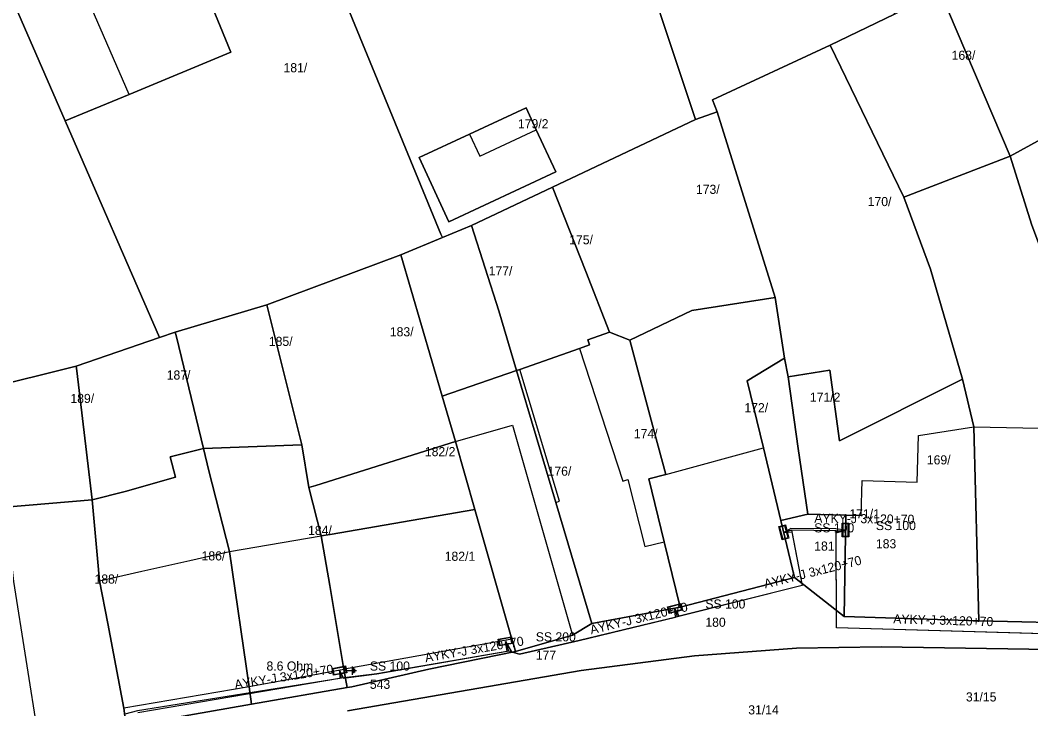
# Model space of a CAD drawing. Extents: x -793400 to -756198, y -1074141 to -1042963.
# Drawn here: x -783672.6 to -783589.5, y -1065252.1 to -1065195.5 of the extents above; entities that cross this region are included whole.
import ezdxf

# ---------------------------------------------------------------- set-up
doc = ezdxf.new("R2010")
doc.units = 0
for name, color, linetype in [('Parcela', 7, 'Continuous'), ('Popiskový text - Parcela', 7, 'Continuous'), ('Popiskový text - Přípojková skříň nn - SJZ', 7, 'Continuous'), ('Popiskový text - Přípojková skříň nn - Typ', 7, 'Continuous'), ('Popiskový text - Uzemnění - Odpor', 7, 'Continuous'), ('Popiskový text - Vedení nn kabelové', 7, 'Continuous'), ('Skříň', 7, 'Continuous'), ('Spojnice nn', 7, 'Continuous'), ('Stavební objekt', 7, 'Continuous'), ('Uzemnění', 7, 'Continuous'), ('Vedení nn kabelové', 7, 'Continuous')]:
    doc.layers.add(name, color=color, linetype=linetype)

msp = doc.modelspace()

# ---------------------------------------------------------------- linework, layer by layer
at = {"layer": 'Parcela'}
for points in [[(-783615.3, -1065203.05), (-783617.06, -1065203.69), (-783628.64, -1065168.91), (-783610.22, -1065163.36), (-783600.72, -1065195.04), (-783605.99, -1065197.59), (-783615.68, -1065202.06)], [(-783635.48, -1065212.41), (-783637.88, -1065213.4), (-783638.01, -1065213.11), (-783652.59, -1065177.6), (-783628.64, -1065168.91), (-783617.06, -1065203.69), (-783628.83, -1065209.24)], [(-783659.84, -1065221.18), (-783661.13, -1065221.62), (-783668.9, -1065203.8), (-783663.64, -1065201.62), (-783655.26, -1065198.14), (-783659.15, -1065188.65), (-783662.03, -1065181.56), (-783658.02, -1065179.74), (-783652.59, -1065177.6), (-783638.01, -1065213.11), (-783637.88, -1065213.4), (-783641.3, -1065214.82), (-783652.31, -1065218.91)], [(-783663.64, -1065201.62), (-783668.9, -1065203.8), (-783675.89, -1065187.8), (-783662.03, -1065181.56), (-783659.15, -1065188.65), (-783655.26, -1065198.14)], [(-783582.95, -1065202.17), (-783591.21, -1065206.69), (-783596.99, -1065193.1), (-783583.72, -1065188.34), (-783565.46, -1065184.47), (-783562.84, -1065196.01)], [(-783683.5, -1065227.58), (-783687.75, -1065229.06), (-783699.64, -1065200.28), (-783675.89, -1065187.8), (-783668.9, -1065203.8), (-783661.13, -1065221.62), (-783667.99, -1065223.97), (-783675.61, -1065225.85)], [(-783591.21, -1065206.69), (-783599.94, -1065210.07), (-783605.99, -1065197.59), (-783600.72, -1065195.04), (-783596.99, -1065193.1)], [(-783557.3, -1065234.49), (-783556.38, -1065246.22), (-783584.39, -1065245.11), (-783584.35, -1065230.9), (-783584.56, -1065230.03), (-783584.78, -1065229.15), (-783586.43, -1065222.48), (-783588, -1065216.15), (-783589.42, -1065212.38), (-783591.21, -1065206.69), (-783582.95, -1065202.17), (-783562.84, -1065196.01), (-783557.84, -1065229.35), (-783557.51, -1065231.83)], [(-783597.74, -1065215.99), (-783595.12, -1065225.03), (-783605.23, -1065230.1), (-783606.04, -1065224.28), (-783609.46, -1065224.84), (-783609.76, -1065223.3), (-783610.52, -1065218.33), (-783615.3, -1065203.05), (-783615.68, -1065202.06), (-783605.99, -1065197.59), (-783599.94, -1065210.07)], [(-783628.54, -1065208), (-783630.16, -1065204.53), (-783631, -1065202.72), (-783635.65, -1065204.89), (-783639.8, -1065206.82), (-783637.34, -1065212.1)], [(-783628.54, -1065208), (-783637.34, -1065212.1), (-783639.8, -1065206.82), (-783635.65, -1065204.89), (-783631, -1065202.72), (-783630.16, -1065204.53)], [(-783617.38, -1065219.39), (-783622.48, -1065221.84), (-783624.13, -1065221.18), (-783626.08, -1065216.18), (-783628.83, -1065209.24), (-783617.06, -1065203.69), (-783615.3, -1065203.05), (-783610.52, -1065218.33)], [(-783584.35, -1065230.9), (-783584.39, -1065245.11), (-783593.79, -1065244.89), (-783594.19, -1065228.95), (-783595.12, -1065225.03), (-783597.74, -1065215.99), (-783599.94, -1065210.07), (-783591.21, -1065206.69), (-783589.42, -1065212.38), (-783588, -1065216.15), (-783586.43, -1065222.48), (-783584.78, -1065229.15), (-783584.56, -1065230.03)], [(-783631.51, -1065224.23), (-783631.79, -1065224.31), (-783633.23, -1065219.42), (-783635.48, -1065212.41), (-783628.83, -1065209.24), (-783626.08, -1065216.18), (-783624.13, -1065221.18), (-783625.93, -1065221.8), (-783625.79, -1065222.22), (-783626.6, -1065222.5)], [(-783631.79, -1065224.31), (-783637.89, -1065226.43), (-783641.3, -1065214.82), (-783637.88, -1065213.4), (-783635.48, -1065212.41), (-783633.23, -1065219.42)], [(-783648.29, -1065233.77), (-783648.87, -1065233.95), (-783649.42, -1065230.44), (-783652.31, -1065218.91), (-783641.3, -1065214.82), (-783637.89, -1065226.43), (-783636.8, -1065230.16)], [(-783608.92, -1065241.34), (-783618.33, -1065243.78), (-783619.65, -1065238.4), (-783620.92, -1065233.24), (-783619.52, -1065232.86), (-783620.49, -1065229.23), (-783622.48, -1065221.84), (-783617.38, -1065219.39), (-783610.52, -1065218.33), (-783609.76, -1065223.3), (-783612.82, -1065225.16), (-783611.49, -1065230.69), (-783610.05, -1065236.65)], [(-783649.42, -1065230.44), (-783657.52, -1065230.72), (-783659.74, -1065221.56), (-783659.84, -1065221.18), (-783652.31, -1065218.91)], [(-783663.95, -1065234.27), (-783666.67, -1065234.95), (-783667.94, -1065224.36), (-783667.99, -1065223.97), (-783661.13, -1065221.62), (-783659.84, -1065221.18), (-783659.74, -1065221.56), (-783657.52, -1065230.72), (-783660.27, -1065231.42), (-783659.82, -1065233.08)], [(-783618.33, -1065243.78), (-783625.58, -1065245.12), (-783628.54, -1065235.17), (-783631.79, -1065224.31), (-783631.51, -1065224.23), (-783626.6, -1065222.5), (-783625.79, -1065222.22), (-783625.93, -1065221.8), (-783624.13, -1065221.18), (-783622.48, -1065221.84), (-783620.49, -1065229.23), (-783619.52, -1065232.86), (-783620.92, -1065233.24), (-783619.65, -1065238.4)], [(-783607.83, -1065236.12), (-783610.05, -1065236.65), (-783611.49, -1065230.69), (-783612.82, -1065225.16), (-783609.76, -1065223.3), (-783609.46, -1065224.84), (-783608.64, -1065230.72)], [(-783666.67, -1065234.95), (-783673.8, -1065235.56), (-783675.53, -1065226.24), (-783675.61, -1065225.85), (-783667.99, -1065223.97), (-783667.94, -1065224.36)], [(-783627.17, -1065246.09), (-783631.88, -1065247.41), (-783632.1, -1065246.62), (-783632.16, -1065246.4), (-783635.2, -1065235.76), (-783636.8, -1065230.16), (-783637.89, -1065226.43), (-783631.79, -1065224.31), (-783628.54, -1065235.17), (-783625.58, -1065245.12)], [(-783606.04, -1065224.28), (-783605.23, -1065230.1), (-783595.12, -1065225.03), (-783594.19, -1065228.95), (-783593.79, -1065244.89), (-783604.86, -1065244.55), (-783604.72, -1065236.2), (-783607.83, -1065236.12), (-783608.64, -1065230.72), (-783609.46, -1065224.84)], [(-783653.56, -1065251.76), (-783663.87, -1065253.57), (-783664.06, -1065252.07), (-783665.38, -1065245.11), (-783666.06, -1065241.6), (-783666.22, -1065239.78), (-783666.67, -1065234.95), (-783663.95, -1065234.27), (-783659.82, -1065233.08), (-783660.27, -1065231.42), (-783657.52, -1065230.72), (-783657.08, -1065232.56), (-783655.37, -1065239.19), (-783653.77, -1065250.32)], [(-783645.72, -1065250.38), (-783653.56, -1065251.76), (-783653.77, -1065250.32), (-783655.37, -1065239.19), (-783657.08, -1065232.56), (-783657.52, -1065230.72), (-783649.42, -1065230.44), (-783648.87, -1065233.95), (-783647.84, -1065237.91), (-783647.14, -1065241.99), (-783645.97, -1065248.89)], [(-783647.11, -1065237.79), (-783647.84, -1065237.91), (-783648.87, -1065233.95), (-783648.29, -1065233.77), (-783636.8, -1065230.16), (-783635.2, -1065235.76)], [(-783663.87, -1065253.57), (-783671.01, -1065254.97), (-783671.09, -1065254.5), (-783673.1, -1065241.67), (-783673.8, -1065235.56), (-783666.67, -1065234.95), (-783666.22, -1065239.78), (-783666.06, -1065241.6), (-783665.38, -1065245.11), (-783664.06, -1065252.07)], [(-783645.33, -1065250.32), (-783645.72, -1065250.38), (-783645.97, -1065248.89), (-783647.14, -1065241.99), (-783647.84, -1065237.91), (-783647.11, -1065237.79), (-783635.2, -1065235.76), (-783632.16, -1065246.4), (-783632.1, -1065246.62), (-783631.88, -1065247.41), (-783638.98, -1065248.88)], [(-783604.72, -1065236.2), (-783604.86, -1065244.55), (-783608.92, -1065241.34), (-783610.05, -1065236.65), (-783607.83, -1065236.12)]]:
    msp.add_lwpolyline(points, close=True, dxfattribs=at)
for points in [[(-783663.87, -1065253.57), (-783653.56, -1065251.76), (-783645.72, -1065250.38), (-783645.33, -1065250.32), (-783638.98, -1065248.88), (-783631.88, -1065247.41), (-783627.17, -1065246.09), (-783625.58, -1065245.12), (-783618.33, -1065243.78), (-783608.92, -1065241.34), (-783604.86, -1065244.55), (-783593.79, -1065244.89), (-783584.39, -1065245.11), (-783556.38, -1065246.22), (-783540.31, -1065245.49), (-783533.99, -1065245.21)], [(-783486.18, -1065252.95), (-783489.01, -1065251.32), (-783491.82, -1065250.1), (-783495.64, -1065249.27), (-783499.12, -1065248.83), (-783556.41, -1065248.29), (-783589.66, -1065247.24), (-783601.8, -1065247.03), (-783608.78, -1065247.15), (-783617.15, -1065247.78), (-783626.46, -1065248.97), (-783645.69, -1065252.29)], [(-783645.69, -1065252.29), (-783626.46, -1065248.97), (-783617.15, -1065247.78), (-783608.78, -1065247.15), (-783601.8, -1065247.03), (-783589.66, -1065247.24), (-783556.41, -1065248.29), (-783499.12, -1065248.83), (-783495.64, -1065249.27), (-783491.82, -1065250.1), (-783489.01, -1065251.32), (-783486.18, -1065252.95)]]:
    msp.add_lwpolyline(points, dxfattribs=at)
at = {"layer": 'Skříň'}
for points in [[(-783609.681, -1065237.014), (-783609.395, -1065238.102), (-783609.939, -1065238.246), (-783610.225, -1065237.158)], [(-783609.464, -1065238.062), (-783609.722, -1065237.083), (-783610.157, -1065237.198), (-783609.899, -1065238.177)], [(-783604.459, -1065236.878), (-783604.459, -1065238.003), (-783605.022, -1065238.002), (-783605.021, -1065236.877)], [(-783604.515, -1065237.946), (-783604.515, -1065236.934), (-783604.965, -1065236.934), (-783604.965, -1065237.946)], [(-783619.376, -1065243.762), (-783618.288, -1065243.475), (-783618.144, -1065244.019), (-783619.232, -1065244.306)], [(-783618.328, -1065243.543), (-783619.307, -1065243.802), (-783619.192, -1065244.237), (-783618.213, -1065243.978)], [(-783633.302, -1065246.408), (-783632.193, -1065246.218), (-783632.098, -1065246.772), (-783633.207, -1065246.962)], [(-783632.239, -1065246.283), (-783633.237, -1065246.454), (-783633.161, -1065246.898), (-783632.163, -1065246.726)], [(-783646.945, -1065248.819), (-783645.84, -1065248.609), (-783645.735, -1065249.161), (-783646.84, -1065249.372)], [(-783645.885, -1065248.674), (-783646.879, -1065248.864), (-783646.795, -1065249.306), (-783645.801, -1065249.117)]]:
    msp.add_lwpolyline(points, close=True, dxfattribs=at)
at = {"layer": 'Spojnice nn'}
for p, q in [((-783609.18, -1065237.45), (-783609.81, -1065237.63)), ((-783605.51, -1065237.5), (-783609.18, -1065237.45)), ((-783605.51, -1065237.5), (-783604.74, -1065237.44)), ((-783618.56, -1065244.56), (-783618.76, -1065243.89)), ((-783632.41, -1065247.38), (-783632.7, -1065246.59)), ((-783646.16, -1065249.62), (-783646.34, -1065248.99)), ((-783646.16, -1065249.62), (-783662.92, -1065252.46))]:
    msp.add_line(p, q, dxfattribs=at)
for points in [[(-783609.18, -1065237.45), (-783608.31, -1065242), (-783618.56, -1065244.56)], [(-783588.37, -1065245.96), (-783605.47, -1065245.48), (-783605.51, -1065237.5)], [(-783618.56, -1065244.56), (-783626.63, -1065246.51), (-783631.53, -1065247.63), (-783632.41, -1065247.38)], [(-783632.41, -1065247.38), (-783643.26, -1065249.25), (-783646.16, -1065249.62)]]:
    msp.add_lwpolyline(points, dxfattribs=at)
at = {"layer": 'Stavební objekt'}
for points in [[(-783655.26, -1065198.14), (-783663.64, -1065201.62), (-783666.74, -1065194.45), (-783665.81, -1065194.06), (-783666.49, -1065192.38), (-783665.09, -1065191.8), (-783665.28, -1065191.25), (-783659.15, -1065188.65)], [(-783630.16, -1065204.53), (-783628.54, -1065208), (-783637.34, -1065212.1), (-783639.8, -1065206.82), (-783635.65, -1065204.89), (-783634.81, -1065206.69)], [(-783626.6, -1065222.5), (-783623.04, -1065233.42), (-783622.62, -1065233.29), (-783621.24, -1065238.79), (-783619.65, -1065238.4), (-783618.33, -1065243.78), (-783625.58, -1065245.12), (-783628.54, -1065235.17), (-783628.24, -1065235.07), (-783631.51, -1065224.23)], [(-783627.17, -1065246.09), (-783631.88, -1065247.41), (-783632.1, -1065246.62), (-783632.16, -1065246.4), (-783635.2, -1065235.76), (-783636.8, -1065230.16), (-783632.12, -1065228.82)], [(-783594.19, -1065228.95), (-783593.79, -1065244.89), (-783604.86, -1065244.55), (-783604.72, -1065236.2), (-783603.45, -1065236.22), (-783603.36, -1065233.37), (-783598.86, -1065233.51), (-783598.75, -1065229.66)], [(-783584.35, -1065230.9), (-783584.39, -1065245.11), (-783593.79, -1065244.89), (-783594.19, -1065228.95), (-783584.78, -1065229.15), (-783584.56, -1065230.03)], [(-783608.92, -1065241.34), (-783618.33, -1065243.78), (-783619.65, -1065238.4), (-783620.92, -1065233.24), (-783619.52, -1065232.86), (-783611.49, -1065230.69), (-783610.05, -1065236.65)], [(-783645.63, -1065248.83), (-783645.97, -1065248.89), (-783647.14, -1065241.99), (-783647.84, -1065237.91), (-783647.11, -1065237.79), (-783635.2, -1065235.76), (-783632.16, -1065246.4)], [(-783645.97, -1065248.89), (-783653.77, -1065250.32), (-783655.37, -1065239.19), (-783647.84, -1065237.91), (-783647.14, -1065241.99)], [(-783653.77, -1065250.32), (-783664.06, -1065252.07), (-783665.38, -1065245.11), (-783666.06, -1065241.6), (-783662.6, -1065240.82), (-783658.65, -1065239.93), (-783655.37, -1065239.19)]]:
    msp.add_lwpolyline(points, close=True, dxfattribs=at)
at = {"layer": 'Uzemnění'}
for p, q in [((-783645.946, -1065248.99), (-783645.261, -1065248.99)), ((-783645.261, -1065249.336), (-783645.261, -1065248.644)), ((-783645.169, -1065249.211), (-783645.169, -1065248.769)), ((-783645.07, -1065249.134), (-783645.07, -1065248.849)), ((-783644.963, -1065249.042), (-783644.963, -1065248.942))]:
    msp.add_line(p, q, dxfattribs=at)
at = {"layer": 'Vedení nn kabelové'}
for points in [[(-783604.74, -1065237.44), (-783605.522, -1065237.35), (-783609.221, -1065237.306), (-783609.81, -1065237.63)], [(-783588.38, -1065245.03), (-783588.519, -1065245.956), (-783605.47, -1065245.48), (-783605.509, -1065237.653), (-783604.74, -1065237.44)], [(-783609.81, -1065237.63), (-783609.152, -1065237.595), (-783608.31, -1065242), (-783618.413, -1065244.523), (-783618.76, -1065243.89)], [(-783632.7, -1065246.59), (-783632.205, -1065247.438), (-783631.53, -1065247.63), (-783626.63, -1065246.51), (-783618.704, -1065244.595), (-783618.76, -1065243.89)], [(-783646.34, -1065248.99), (-783646.004, -1065249.6), (-783643.26, -1065249.25), (-783632.556, -1065247.405), (-783632.7, -1065246.59)], [(-783646.34, -1065248.99), (-783646.305, -1065249.643), (-783662.936, -1065252.311), (-783663.98, -1065252.57)]]:
    msp.add_lwpolyline(points, dxfattribs=at)

# ---------------------------------------------------------------- texts
at = {"layer": 'Popiskový text - Parcela'}
for s, p in [('168/', (-783596.015, -1065198.78)), ('181/', (-783650.94, -1065199.805)), ('179/2', (-783631.67, -1065204.411)), ('173/', (-783617.033, -1065209.802)), ('170/', (-783602.916, -1065210.809)), ('175/', (-783627.456, -1065213.947)), ('177/', (-783634.074, -1065216.51)), ('183/', (-783642.2, -1065221.514)), ('185/', (-783652.145, -1065222.301)), ('187/', (-783660.543, -1065225.068)), ('189/', (-783668.458, -1065226.993)), ('171/2', (-783607.668, -1065226.888)), ('172/', (-783613.052, -1065227.754)), ('174/', (-783622.139, -1065229.888)), ('182/2', (-783639.318, -1065231.364)), ('169/', (-783598.053, -1065232.041)), ('176/', (-783629.229, -1065232.969)), ('171/1', (-783604.422, -1065236.478)), ('184/', (-783648.921, -1065237.839)), ('186/', (-783657.677, -1065239.933)), ('182/1', (-783637.689, -1065239.967)), ('188/', (-783666.477, -1065241.839)), ('31/15', (-783594.839, -1065251.528)), ('31/14', (-783612.733, -1065252.592))]:
    msp.add_text(s, height=0.75, dxfattribs=at).set_placement(p)
at = {"layer": 'Popiskový text - Přípojková skříň nn - SJZ'}
for s, p in [('183', (-783602.24, -1065238.94)), ('181', (-783607.31, -1065239.13)), ('180', (-783616.26, -1065245.39)), ('177', (-783630.2, -1065248.09)), ('543', (-783643.84, -1065250.49))]:
    msp.add_text(s, height=0.75, dxfattribs=at).set_placement(p)
at = {"layer": 'Popiskový text - Přípojková skříň nn - Typ'}
for s, p in [('SS 100', (-783607.31, -1065237.63)), ('SS 100', (-783602.24, -1065237.44)), ('SS 100', (-783616.26, -1065243.89)), ('SS 200', (-783630.2, -1065246.59)), ('SS 100', (-783643.84, -1065248.99))]:
    msp.add_text(s, height=0.75, dxfattribs=at).set_placement(p)
at = {"layer": 'Popiskový text - Uzemnění - Odpor'}
msp.add_text('8.6 Ohm', height=0.75, dxfattribs=at).set_placement((-783652.34, -1065248.99))
at = {"layer": 'Popiskový text - Vedení nn kabelové'}
for rotation, p in [(359.30183, (-783607.308, -1065236.829)), (14.03747, (-783611.338, -1065242.241)), (13.5791, (-783625.644, -1065246.014)), (358.3851, (-783600.824, -1065245.11)), (9.79758, (-783639.249, -1065248.305)), (9.11003, (-783654.908, -1065250.517))]:
    msp.add_text('AYKY-J 3x120+70', height=0.75, rotation=rotation, dxfattribs=at).set_placement(p)

doc.saveas('drawing.dxf')
